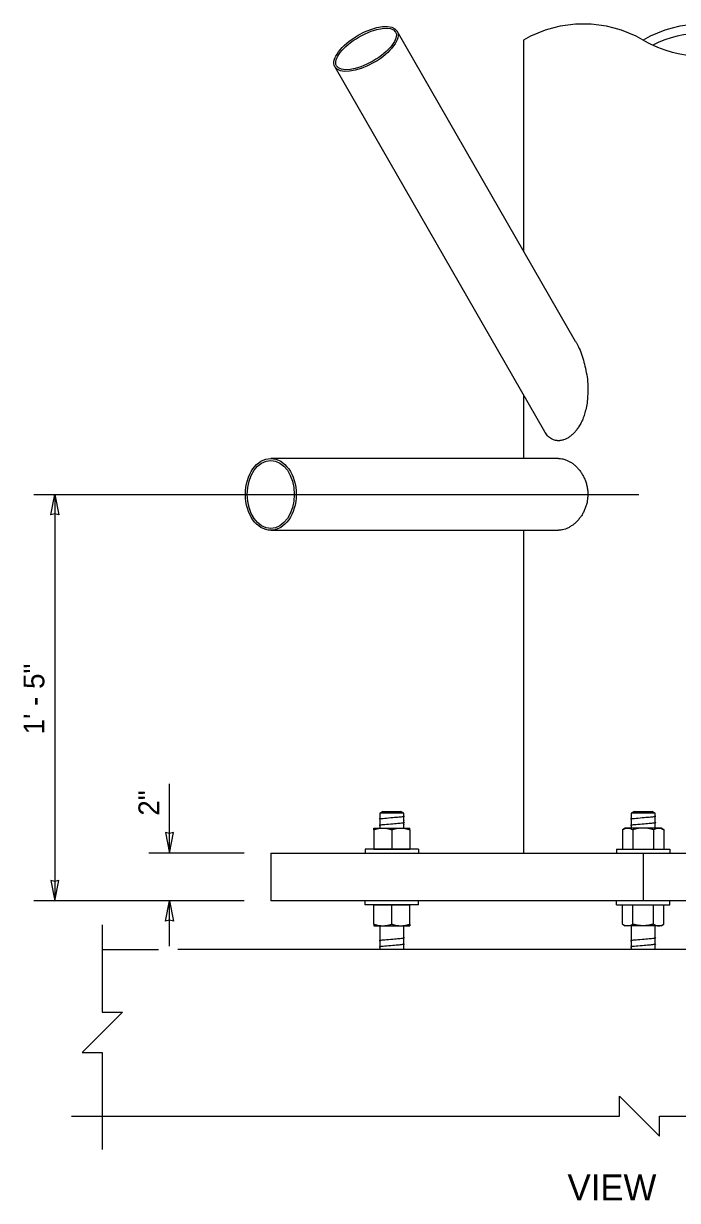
# Model space of a CAD drawing. Extents: x 99862 to 104211, y 98939 to 111076.
# Drawn here: x 101524 to 102028, y 109418 to 110325 of the extents above; entities that cross this region are included whole.
import ezdxf

# ---------------------------------------------------------------- set-up
doc = ezdxf.new("R2010")
doc.units = 0
for name, color, linetype in [('Level 11', 7, 'Continuous'), ('Level 15', 7, 'Continuous'), ('Level 2', 7, 'Continuous'), ('Level 20', 7, 'Continuous'), ('Level 3', 7, 'Continuous'), ('Level 4', 7, 'Continuous'), ('Level 62', 7, 'Continuous'), ('Level 7', 7, 'Continuous'), ('Level 9', 7, 'Continuous')]:
    doc.layers.add(name, color=color, linetype=linetype)

msp = doc.modelspace()

# ---------------------------------------------------------------- linework, layer by layer
at = {"layer": 'Level 11'}
for p, q in [((101949.16, 110079.57), (101811.83, 110318.7)), ((101763.91, 110291.18), (101925.28, 110010.21)), ((101935.98, 109989.45), (101714.56, 109989.45)), ((101714.56, 109934.19), (101935.98, 109934.19))]:
    msp.add_line(p, q, dxfattribs=at)
for centre, major_axis, ratio in [((101787.87, 110304.94), (23.96, 13.76), 0.439922), ((101787.87, 110304.94), (22.72, 13.05), 0.409435), ((101714.56, 109961.82), (0, -27.63), 0.707107), ((101714.56, 109961.82), (0, -26.2), 0.691164)]:
    msp.add_ellipse(centre, major_axis=major_axis, ratio=ratio, dxfattribs=at)
msp.add_ellipse((101951.13, 110020.67), major_axis=(23.96, 13.76), ratio=0.445792, start_param=3.748252, end_param=3.855094, dxfattribs=at)
for points in [[(101948.95, 110079.94), (101949.26, 110079.4), (101949.57, 110078.85), (101949.86, 110078.3), (101952.72, 110072.92), (101954.84, 110066.86), (101956.28, 110060.69), (101957.84, 110054.03), (101958.65, 110047.04), (101958.49, 110040.14), (101958.37, 110034.84), (101957.66, 110029.48), (101956.2, 110024.46), (101955.11, 110020.76), (101953.58, 110017.16), (101951.62, 110014.03), (101950.08, 110011.56), (101948.24, 110009.33), (101946.22, 110007.58), (101944.18, 110005.82), (101941.91, 110004.49), (101939.67, 110003.8), (101938.79, 110003.53), (101937.9, 110003.35), (101937.03, 110003.28)], [(101934.94, 110003.28), (101933.11, 110003.45), (101931.37, 110004.09), (101929.83, 110005.14), (101928.31, 110006.18), (101926.95, 110007.63), (101925.81, 110009.36), (101925.57, 110009.72), (101925.34, 110010.1), (101925.12, 110010.49)], [(101935.98, 109989.45), (101938.11, 109989.45), (101940.38, 109988.94), (101942.59, 109987.97), (101944.79, 109987), (101946.99, 109985.55), (101948.97, 109983.73), (101951.01, 109981.87), (101952.87, 109979.57), (101954.37, 109977.01), (101955.9, 109974.4), (101957.09, 109971.44), (101957.78, 109968.38), (101958.45, 109965.4), (101958.67, 109962.24), (101958.4, 109959.19), (101958.13, 109956.24), (101957.42, 109953.31), (101956.33, 109950.62), (101955.23, 109947.89), (101953.73, 109945.34), (101951.99, 109943.15), (101950.18, 109940.87), (101948.06, 109938.92), (101945.85, 109937.46), (101943.62, 109935.99), (101941.24, 109934.97), (101938.94, 109934.5), (101937.95, 109934.3), (101936.95, 109934.2), (101935.98, 109934.2)]]:
    msp.add_open_spline(points, degree=3, dxfattribs=at)
at = {"layer": 'Level 15'}
for p, q in [((101532.28, 109961.82), (101997.69, 109961.82)), ((101548.28, 109961.82), (101548.28, 109648.69)), ((101636.68, 109685.53), (101636.68, 109738.88)), ((101694.18, 109685.53), (101620.68, 109685.53)), ((101694.18, 109648.69), (101532.28, 109648.69)), ((101636.68, 109613.69), (101636.68, 109648.69))]:
    msp.add_line(p, q, dxfattribs=at)
for points in [[(101548.28, 109961.82), (101551.36, 109946.1), (101548.28, 109946.82), (101545.19, 109946.1)], [(101636.68, 109685.53), (101639.77, 109701.25), (101636.68, 109700.53), (101633.6, 109701.25)], [(101548.28, 109648.69), (101551.36, 109664.42), (101548.28, 109663.69), (101545.19, 109664.42)], [(101636.68, 109648.69), (101639.77, 109632.97), (101636.68, 109633.7), (101633.6, 109632.97)]]:
    msp.add_lwpolyline(points, close=True, dxfattribs=at)
for points in [[(101584.87, 109630.31), (101584.87, 109562.89), (101600.35, 109562.89), (101569.38, 109531.92), (101584.87, 109531.92), (101584.87, 109457.07)], [(101561.2, 109482.75), (101982.85, 109482.75), (101982.85, 109498.24), (102013.82, 109467.27), (102013.82, 109482.75), (102479.85, 109482.75)]]:
    msp.add_lwpolyline(points, dxfattribs=at)
at = {"layer": 'Level 2'}
for points in [[(101797.99, 109706.86), (101797.98, 109706.9), (101798.01, 109706.94), (101798.63, 109707.24), (101801.51, 109707.49), (101808.95, 109708.2), (101813.39, 109708.48), (101816.95, 109708.93), (101817.57, 109709.08), (101817.38, 109709.29)], [(101797.99, 109711.66), (101798, 109711.69), (101798.03, 109711.72), (101798.62, 109712.01), (101801.49, 109712.27), (101808.93, 109712.97), (101813.37, 109713.25), (101816.86, 109713.69), (101817.49, 109713.84), (101817.41, 109714.02)], [(101991.47, 109706.86), (101991.45, 109706.9), (101991.49, 109706.94), (101992.11, 109707.24), (101994.98, 109707.49), (102002.42, 109708.2), (102006.86, 109708.48), (102010.43, 109708.93), (102011.04, 109709.08), (102010.85, 109709.29)], [(101991.46, 109711.66), (101991.47, 109711.69), (101991.51, 109711.72), (101992.1, 109712.01), (101994.96, 109712.27), (102002.4, 109712.97), (102006.84, 109713.25), (102010.33, 109713.69), (102010.96, 109713.84), (102010.88, 109714.02)], [(101797.99, 109613.23), (101797.98, 109613.27), (101798.01, 109613.31), (101798.63, 109613.61), (101801.51, 109613.86), (101808.95, 109614.57), (101813.39, 109614.85), (101816.95, 109615.3), (101817.57, 109615.45), (101817.38, 109615.66)], [(101797.99, 109618.03), (101798, 109618.06), (101798.03, 109618.09), (101798.62, 109618.38), (101801.49, 109618.64), (101808.93, 109619.34), (101813.37, 109619.62), (101816.86, 109620.06), (101817.49, 109620.21), (101817.41, 109620.39)], [(101991.45, 109613.23), (101991.43, 109613.27), (101991.47, 109613.31), (101992.09, 109613.61), (101994.96, 109613.86), (102002.41, 109614.57), (102006.84, 109614.85), (102010.41, 109615.3), (102011.03, 109615.45), (102010.84, 109615.66)], [(101991.45, 109618.03), (101991.45, 109618.06), (101991.49, 109618.09), (101992.08, 109618.38), (101994.95, 109618.64), (102002.38, 109619.34), (102006.83, 109619.62), (102010.32, 109620.06), (102010.94, 109620.21), (102010.86, 109620.39)]]:
    msp.add_open_spline(points, degree=3, dxfattribs=at)
at = {"layer": 'Level 3'}
for p, q in [((101584.87, 109611.09), (101628.2, 109611.09)), ((101643.11, 109611.46), (102447.44, 109611.46))]:
    msp.add_line(p, q, dxfattribs=at)
at = {"layer": 'Level 4'}
for p, q in [((101909, 110311.79), (101909, 110149.5)), ((101909, 110038.54), (101909, 109989.45)), ((101909, 109934.19), (101909, 109685.53)), ((102001.1, 109685.53), (102001.1, 109648.69))]:
    msp.add_line(p, q, dxfattribs=at)
for centre, radius, start, end in [((101955.05, 110232.03), 92.1, 60, 120), ((102047.15, 110232.03), 92.1, 60, 120), ((102047.15, 110232.03), 85.19, 63.02278, 116.97722), ((102047.15, 110391.55), 92.1, 240, 300)]:
    msp.add_arc(centre, radius, start, end, dxfattribs=at)
at = {"layer": 'Level 62'}
for points in [[(101816.91, 109710.44), (101816.95, 109710.41), (101816.95, 109710.38), (101816.91, 109710.35)], [(101816.91, 109707.36), (101816.95, 109707.33), (101816.95, 109707.3), (101816.91, 109707.27)], [(102010.37, 109711.17), (102010.4, 109711.15), (102010.4, 109711.12), (102010.37, 109711.09)], [(102010.37, 109708.1), (102010.39, 109708.08), (102010.39, 109708.05), (102010.37, 109708.03)]]:
    msp.add_open_spline(points, degree=3, dxfattribs=at)
at = {"layer": 'Level 7'}
for p, q in [((101714.56, 109685.53), (101714.56, 109648.69)), ((101714.56, 109685.53), (102001.1, 109685.53)), ((102001.1, 109685.53), (102287.64, 109685.53)), ((102001.1, 109648.69), (101714.56, 109648.69)), ((102287.64, 109648.69), (102001.1, 109648.69))]:
    msp.add_line(p, q, dxfattribs=at)
at = {"layer": 'Level 9'}
for p, q in [((101800.7, 109717.51), (101798.49, 109716.23)), ((101798.49, 109716.24), (101798.49, 109704.72)), ((101800.7, 109717.51), (101814.7, 109717.51)), ((101814.7, 109717.51), (101814.7, 109717.51)), ((101816.91, 109716.23), (101814.7, 109717.51)), ((101816.91, 109704.72), (101816.91, 109716.24)), ((101994.17, 109717.51), (101991.95, 109716.22)), ((101991.95, 109716.24), (101991.95, 109704.72)), ((101994.17, 109717.51), (102008.17, 109717.51)), ((102010.37, 109716.24), (102008.17, 109717.51)), ((102010.37, 109704.72), (102010.37, 109716.24)), ((101793.85, 109704.72), (101800.51, 109704.72)), ((101793.85, 109703.48), (101793.85, 109688.6)), ((101800.51, 109704.72), (101801.01, 109704.72)), ((101801.01, 109704.72), (101814.24, 109704.72)), ((101807.66, 109703.49), (101807.66, 109688.6)), ((101814.24, 109704.72), (101814.89, 109704.72)), ((101814.89, 109704.72), (101821.47, 109704.72)), ((101821.47, 109703.49), (101821.47, 109688.6)), ((101987.27, 109704.72), (101985.14, 109703.48)), ((101985.14, 109703.48), (101985.14, 109688.6)), ((102001.09, 109704.72), (101987.27, 109704.72)), ((101993.11, 109703.48), (101993.11, 109688.6)), ((102012.91, 109704.72), (102001.09, 109704.72)), ((102009.06, 109703.48), (102009.06, 109688.6)), ((102012.91, 109704.72), (102013.19, 109704.72)), ((102014.9, 109704.72), (102013.19, 109704.72)), ((102017.04, 109703.49), (102014.9, 109704.72)), ((102017.04, 109703.49), (102017.04, 109688.6)), ((101828.13, 109688.6), (101787.2, 109688.6)), ((101787.2, 109688.6), (101787.2, 109685.53)), ((101793.85, 109688.6), (101807.66, 109688.6)), ((101807.66, 109688.6), (101821.47, 109688.6)), ((101828.13, 109688.6), (101828.13, 109685.53)), ((101980.62, 109688.6), (102021.55, 109688.6)), ((101980.62, 109688.6), (101980.62, 109685.53)), ((101985.14, 109688.6), (101993.11, 109688.6)), ((101993.11, 109688.6), (102009.06, 109688.6)), ((102009.06, 109688.6), (102017.04, 109688.6)), ((102021.55, 109688.6), (102021.55, 109685.53)), ((101787.2, 109645.62), (101787.2, 109648.69)), ((101828.13, 109645.62), (101787.2, 109645.62)), ((101793.85, 109645.62), (101807.66, 109645.62)), ((101793.85, 109630.74), (101793.85, 109645.62)), ((101807.66, 109645.62), (101821.47, 109645.62)), ((101807.66, 109630.74), (101807.66, 109645.62)), ((101821.47, 109630.74), (101821.47, 109645.62)), ((101828.13, 109645.62), (101828.13, 109648.69)), ((101980.62, 109645.62), (101980.62, 109648.69)), ((101980.62, 109645.62), (101980.62, 109645.62)), ((101980.62, 109645.62), (102021.55, 109645.62)), ((101985.14, 109645.62), (101993.11, 109645.62)), ((101985.14, 109630.74), (101985.14, 109645.62)), ((101993.11, 109630.74), (101993.11, 109645.62)), ((101993.11, 109645.62), (102009.06, 109645.62)), ((102009.06, 109645.62), (102017.04, 109645.62)), ((102009.06, 109630.74), (102009.06, 109645.62)), ((102017.04, 109630.74), (102017.04, 109645.62)), ((102021.55, 109645.62), (102021.55, 109648.69)), ((101793.85, 109629.51), (101800.51, 109629.51)), ((101798.49, 109629.51), (101798.49, 109611.09)), ((101800.51, 109629.51), (101801.01, 109629.51)), ((101801.01, 109629.51), (101814.24, 109629.51)), ((101814.24, 109629.51), (101814.89, 109629.51)), ((101814.89, 109629.51), (101821.47, 109629.51)), ((101816.91, 109611.09), (101816.91, 109629.51)), ((101985.14, 109630.74), (101987.27, 109629.51)), ((101987.26, 109629.51), (101987.27, 109629.51)), ((102001.09, 109629.51), (101987.27, 109629.51)), ((101991.8, 109629.51), (101991.8, 109611.09)), ((101991.95, 109629.51), (101991.95, 109611.09)), ((102012.91, 109629.51), (102001.09, 109629.51)), ((102010.37, 109611.09), (102010.37, 109629.51)), ((102012.91, 109629.51), (102013.19, 109629.51)), ((102014.9, 109629.51), (102013.19, 109629.51)), ((102014.9, 109629.51), (102017.04, 109630.74))]:
    msp.add_line(p, q, dxfattribs=at)
for points, degree in [([(101816.91, 109716.23), (101816.91, 109716.23), (101816.87, 109716.23), (101816.81, 109716.23), (101816.65, 109716.23), (101816.32, 109716.24), (101815.84, 109716.24), (101815.35, 109716.24), (101814.71, 109716.24), (101813.95, 109716.24), (101813.19, 109716.24), (101812.31, 109716.24), (101811.36, 109716.24), (101810.41, 109716.24), (101809.39, 109716.24), (101808.36, 109716.24), (101807.33, 109716.24), (101806.27, 109716.24), (101805.28, 109716.24), (101804.28, 109716.24), (101803.32, 109716.24), (101802.47, 109716.24), (101801.63, 109716.24), (101800.87, 109716.24), (101800.26, 109716.24), (101799.65, 109716.24), (101799.18, 109716.24), (101798.88, 109716.23), (101798.62, 109716.23), (101798.49, 109716.23), (101798.49, 109716.23)], 3), ([(102010.36, 109716.24), (102010.36, 109716.24), (102010.26, 109716.24), (102010.04, 109716.24), (102009.77, 109716.24), (102009.32, 109716.24), (102008.74, 109716.24), (102008.16, 109716.24), (102007.42, 109716.24), (102006.58, 109716.24), (102005.75, 109716.24), (102004.8, 109716.24), (102003.81, 109716.23), (102002.83, 109716.23), (102001.78, 109716.23), (102000.75, 109716.23), (101999.72, 109716.23), (101998.68, 109716.23), (101997.72, 109716.23), (101996.77, 109716.23), (101995.86, 109716.23), (101995.09, 109716.23), (101994.31, 109716.22), (101993.64, 109716.22), (101993.14, 109716.22), (101992.63, 109716.22), (101992.27, 109716.22), (101992.09, 109716.22), (101991.99, 109716.22), (101991.95, 109716.22), (101991.95, 109716.22)], 3), ([(101793.85, 109704.72), (101793.85, 109704.72), (101793.85, 109704.72), (101793.85, 109704.72)], 2), ([(101793.85, 109703.48), (101793.85, 109704.23), (101793.85, 109704.72), (101793.85, 109704.72)], 2), ([(101793.85, 109703.48), (101796.03, 109704.21), (101798.24, 109704.69), (101800.51, 109704.72)], 2), ([(101801.01, 109704.72), (101803.27, 109704.69), (101805.49, 109704.21), (101807.66, 109703.49)], 2), ([(101807.66, 109703.49), (101809.81, 109704.2), (101812, 109704.68), (101814.24, 109704.72)], 2), ([(101814.89, 109704.72), (101817.13, 109704.68), (101819.32, 109704.2), (101821.47, 109703.49)], 2), ([(101821.47, 109703.49), (101821.47, 109704.2), (101821.47, 109704.68), (101821.47, 109704.72)], 2), ([(101985.14, 109703.48), (101986.44, 109704.23), (101987.76, 109704.71), (101990.47, 109704.72), (101991.81, 109704.24), (101993.11, 109703.48)], 3), ([(101985.14, 109703.48), (101985.14, 109703.48), (101985.14, 109703.48), (101985.14, 109703.48)], 2), ([(102001.09, 109704.72), (101998.39, 109704.72), (101995.69, 109704.23), (101993.11, 109703.48)], 2), ([(102009.06, 109703.48), (102006.47, 109704.23), (102003.78, 109704.72), (102001.09, 109704.72)], 2), ([(102009.06, 109703.48), (102010.32, 109704.21), (102011.6, 109704.69), (102012.91, 109704.72)], 2), ([(102013.19, 109704.72), (102014.5, 109704.69), (102015.78, 109704.21), (102017.04, 109703.49)], 2), ([(101793.85, 109630.74), (101793.85, 109629.99), (101793.85, 109629.51), (101793.85, 109629.51)], 2), ([(101793.85, 109630.74), (101796.03, 109630.01), (101798.24, 109629.54), (101800.51, 109629.51)], 2), ([(101793.85, 109629.51), (101793.85, 109629.51), (101793.85, 109629.51), (101793.85, 109629.51)], 2), ([(101801.01, 109629.51), (101803.27, 109629.54), (101805.49, 109630.01), (101807.66, 109630.74)], 2), ([(101807.66, 109630.74), (101809.81, 109630.02), (101812, 109629.55), (101814.24, 109629.51)], 2), ([(101814.89, 109629.51), (101817.13, 109629.55), (101819.32, 109630.02), (101821.47, 109630.74)], 2), ([(101821.47, 109630.74), (101821.47, 109630.02), (101821.47, 109629.54), (101821.47, 109629.51)], 2), ([(101985.13, 109630.74), (101985.26, 109630.66), (101985.39, 109630.59), (101985.51, 109630.52)], 2), ([(101985.14, 109630.74), (101985.14, 109630.74), (101985.14, 109630.74), (101985.14, 109630.74)], 2), ([(101985.14, 109630.74), (101986.44, 109629.99), (101987.76, 109629.51), (101990.47, 109629.51), (101991.81, 109629.99), (101993.11, 109630.74)], 3), ([(102001.09, 109629.51), (101998.39, 109629.51), (101995.69, 109630), (101993.11, 109630.74)], 2), ([(102009.06, 109630.74), (102006.47, 109629.99), (102003.78, 109629.51), (102001.09, 109629.51)], 2), ([(102009.06, 109630.74), (102010.32, 109630.01), (102011.6, 109629.54), (102012.91, 109629.51)], 2), ([(102013.19, 109629.51), (102014.5, 109629.54), (102015.78, 109630.01), (102017.04, 109630.74)], 2), ([(102017.04, 109630.74), (102017.04, 109630.74), (102017.04, 109630.74), (102017.03, 109630.74)], 2)]:
    msp.add_open_spline(points, degree=degree, dxfattribs=at)

# ---------------------------------------------------------------- texts
at = {"layer": 'Level 20'}
for s, p in [('1\' - 5"', (101540.28, 109776.92)), ('2"', (101628.68, 109714.29))]:
    msp.add_text(s, height=16, rotation=90, dxfattribs=at).set_placement(p)
msp.add_text('VIEW', height=20, dxfattribs=at).set_placement((101942.94, 109417.86))

doc.saveas('drawing.dxf')
